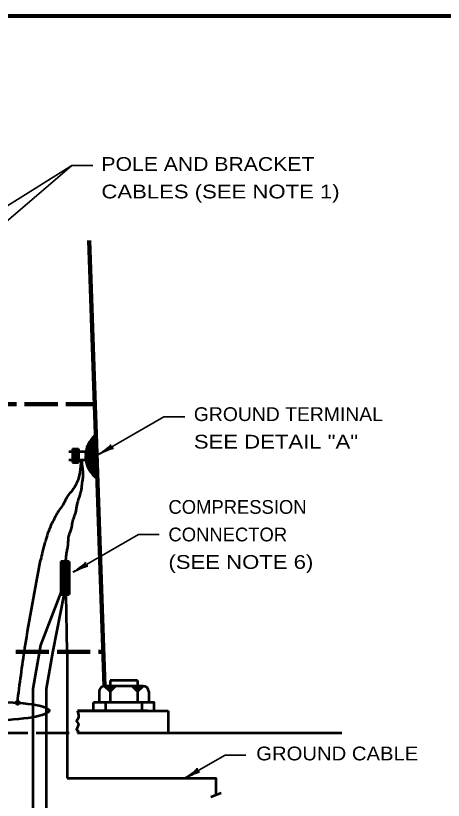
# Model space of a CAD drawing. Extents: x -217 to 639, y -295 to 249.
# Drawn here: x 144.4 to 237.5, y 71.4 to 242.4 of the extents above; entities that cross this region are included whole.
import ezdxf

# ---------------------------------------------------------------- set-up
doc = ezdxf.new("R2010")
doc.units = 0
doc.header["$LTSCALE"] = 1.2
doc.linetypes.add('LONG_DASHED', pattern=[7.5, 6, -1.5])
doc.layers.add('1', color=7, linetype='Continuous', lineweight=53)

msp = doc.modelspace()

# ---------------------------------------------------------------- linework, layer by layer
at = {"layer": '1', "lineweight": 35}
msp.add_line((156.575, 209.728), (133.572, 190.088), dxfattribs=at)
at = {"layer": '1', "lineweight": 90}
msp.add_line((163.725, 96.277), (160.333, 193.418), dxfattribs=at)
at = {"layer": '1', "linetype": 'LONG_DASHED', "lineweight": 90}
for p, q in [((110.301, 157.712), (161.58, 157.712)), ((108.394, 103.712), (163.331, 103.712))]:
    msp.add_line(p, q, dxfattribs=at)
at = {"layer": '1'}
for p, q in [((161.978, 141.739), (161.559, 150.715)), ((161.658, 150.863), (162.028, 141.739)), ((159.66, 147.337), (155.912, 147.337)), ((156.743, 147.995), (156.743, 144.995)), ((156.743, 147.995), (158.023, 147.995)), ((156.743, 147.967), (158.023, 147.967)), ((156.743, 147.959), (158.023, 147.959)), ((156.743, 147.937), (158.023, 147.937)), ((156.743, 147.892), (158.023, 147.892)), ((156.743, 147.884), (158.023, 147.884)), ((156.743, 147.854), (158.023, 147.854)), ((156.743, 147.832), (158.023, 147.832)), ((156.743, 147.832), (158.023, 147.832)), ((156.743, 147.802), (158.023, 147.802)), ((156.743, 147.794), (158.023, 147.794)), ((156.743, 147.794), (158.023, 147.794)), ((156.743, 147.779), (158.023, 147.779)), ((156.743, 147.764), (158.023, 147.764)), ((156.743, 147.749), (158.023, 147.749)), ((156.743, 147.726), (158.023, 147.726)), ((156.743, 147.696), (158.023, 147.696)), ((156.743, 147.689), (158.023, 147.689)), ((156.743, 147.681), (158.023, 147.681)), ((156.743, 147.644), (158.023, 147.644)), ((156.743, 147.629), (158.023, 147.629)), ((156.743, 147.629), (158.023, 147.629)), ((156.743, 147.614), (158.023, 147.614)), ((156.743, 147.606), (158.023, 147.606)), ((156.743, 147.598), (158.023, 147.598)), ((156.743, 147.598), (158.023, 147.598)), ((156.743, 147.576), (158.023, 147.576)), ((156.743, 147.553), (158.023, 147.553)), ((156.743, 147.553), (158.023, 147.553)), ((156.743, 147.538), (158.023, 147.538)), ((156.743, 147.508), (158.023, 147.508)), ((156.743, 147.508), (158.023, 147.508)), ((156.743, 147.486), (158.023, 147.486)), ((156.743, 147.471), (158.023, 147.471)), ((156.743, 147.471), (158.023, 147.471)), ((156.743, 147.441), (158.023, 147.441)), ((156.743, 147.441), (158.023, 147.441)), ((156.743, 147.411), (158.023, 147.411)), ((156.743, 147.403), (158.023, 147.403)), ((156.743, 147.403), (158.023, 147.403)), ((156.743, 147.38), (158.023, 147.38)), ((156.743, 147.373), (158.023, 147.373)), ((156.743, 147.35), (158.023, 147.35)), ((156.743, 147.343), (158.023, 147.343)), ((156.743, 147.305), (158.023, 147.305)), ((156.743, 147.298), (158.023, 147.298)), ((156.743, 147.29), (158.023, 147.29)), ((156.743, 147.29), (158.023, 147.29)), ((156.743, 147.275), (158.023, 147.275)), ((156.743, 147.23), (158.023, 147.23)), ((156.743, 147.23), (158.023, 147.23)), ((156.743, 147.222), (158.023, 147.222)), ((156.743, 147.222), (158.023, 147.222)), ((156.743, 147.2), (158.023, 147.2)), ((156.743, 147.162), (158.023, 147.162)), ((156.743, 147.162), (158.023, 147.162)), ((156.743, 147.147), (158.023, 147.147)), ((156.743, 147.11), (158.023, 147.11)), ((158.023, 147.995), (158.023, 144.995)), ((159.648, 145.537), (155.912, 145.537)), ((156.743, 147.072), (158.023, 147.072)), ((156.743, 147.035), (158.023, 147.035)), ((156.743, 147.019), (158.023, 147.019)), ((156.743, 147.004), (158.023, 147.004)), ((156.743, 146.982), (158.023, 146.982)), ((156.743, 146.944), (158.023, 146.944)), ((156.743, 146.907), (158.023, 146.907)), ((156.743, 146.892), (158.023, 146.892)), ((156.743, 146.862), (158.023, 146.862)), ((156.743, 146.862), (158.023, 146.862)), ((156.743, 146.839), (158.023, 146.839)), ((156.743, 146.816), (158.023, 146.816)), ((156.743, 146.809), (158.023, 146.809)), ((156.743, 146.786), (158.023, 146.786)), ((156.743, 146.786), (158.023, 146.786)), ((156.743, 146.741), (158.023, 146.741)), ((156.743, 146.734), (158.023, 146.734)), ((156.743, 146.696), (158.023, 146.696)), ((156.743, 146.681), (158.023, 146.681)), ((156.743, 146.666), (158.023, 146.666)), ((156.743, 146.621), (158.023, 146.621)), ((156.743, 146.621), (158.023, 146.621)), ((156.743, 146.576), (158.023, 146.576)), ((156.743, 146.553), (158.023, 146.553)), ((156.743, 146.538), (158.023, 146.538)), ((156.743, 146.508), (158.023, 146.508)), ((156.743, 146.508), (158.023, 146.508)), ((156.743, 146.471), (158.023, 146.471)), ((156.743, 146.44), (158.023, 146.44)), ((156.743, 146.395), (158.023, 146.395)), ((156.743, 146.358), (158.023, 146.358)), ((156.743, 146.313), (158.023, 146.313)), ((156.743, 146.29), (158.023, 146.29)), ((156.743, 146.26), (158.023, 146.26)), ((156.743, 146.222), (158.023, 146.222)), ((156.743, 146.2), (158.023, 146.2)), ((156.743, 146.155), (158.023, 146.155)), ((156.743, 146.125), (158.023, 146.125)), ((156.743, 146.102), (158.023, 146.102)), ((156.743, 146.079), (158.023, 146.079)), ((156.743, 146.079), (158.023, 146.079)), ((156.743, 146.049), (158.023, 146.049)), ((156.743, 146.027), (158.023, 146.027)), ((156.743, 146.027), (158.023, 146.027)), ((156.743, 146.004), (158.023, 146.004)), ((156.743, 145.974), (158.023, 145.974)), ((156.743, 145.967), (158.023, 145.967)), ((156.743, 145.929), (158.023, 145.929)), ((156.743, 145.929), (158.023, 145.929)), ((156.743, 145.914), (158.023, 145.914)), ((156.743, 145.906), (158.023, 145.906)), ((156.743, 145.884), (158.023, 145.884)), ((156.743, 145.861), (158.023, 145.861)), ((156.743, 145.861), (158.023, 145.861)), ((156.743, 145.831), (158.023, 145.831)), ((156.743, 145.809), (158.023, 145.809)), ((156.743, 145.771), (158.023, 145.771)), ((156.743, 145.741), (158.023, 145.741)), ((156.743, 145.719), (158.023, 145.719)), ((156.743, 145.704), (158.023, 145.704)), ((156.743, 145.681), (158.023, 145.681)), ((156.743, 145.643), (158.023, 145.643)), ((156.743, 145.606), (158.023, 145.606)), ((156.743, 145.576), (158.023, 145.576)), ((156.743, 145.561), (158.023, 145.561)), ((156.743, 145.553), (158.023, 145.553)), ((156.743, 145.508), (158.023, 145.508)), ((156.743, 145.47), (158.023, 145.47)), ((156.743, 145.425), (158.023, 145.425)), ((156.743, 145.403), (158.023, 145.403)), ((156.743, 145.35), (158.023, 145.35)), ((156.743, 145.328), (158.023, 145.328)), ((156.743, 145.312), (158.023, 145.312)), ((156.743, 145.267), (158.023, 145.267)), ((156.743, 145.237), (158.023, 145.237)), ((156.743, 145.192), (158.023, 145.192)), ((156.743, 145.17), (158.023, 145.17)), ((156.743, 145.139), (158.023, 145.139)), ((156.743, 145.109), (158.023, 145.109)), ((156.743, 145.072), (158.023, 145.072)), ((156.743, 145.064), (158.023, 145.064)), ((156.743, 145.042), (158.023, 145.042)), ((156.743, 145.012), (158.023, 145.012)), ((156.743, 144.995), (158.023, 144.995)), ((156.007, 123.399), (154.207, 123.399)), ((154.357, 123.399), (154.357, 116.199)), ((154.477, 123.399), (154.477, 116.199)), ((154.568, 123.399), (154.568, 116.199)), ((154.628, 123.399), (154.628, 116.199)), ((154.748, 123.399), (154.748, 116.199)), ((154.838, 123.399), (154.838, 116.199)), ((154.899, 123.399), (154.899, 116.199)), ((155.019, 123.399), (155.019, 116.199)), ((155.019, 123.399), (155.019, 116.199)), ((155.079, 123.399), (155.079, 116.199)), ((155.199, 123.399), (155.199, 116.199)), ((155.199, 123.399), (155.199, 116.199)), ((155.26, 123.399), (155.26, 116.199)), ((155.407, 116.199), (155.407, 123.399)), ((155.485, 116.199), (155.485, 123.399)), ((155.561, 116.199), (155.561, 123.399)), ((155.622, 116.199), (155.622, 123.399)), ((155.698, 116.199), (155.698, 123.399)), ((155.759, 116.199), (155.759, 123.399)), ((155.85, 116.199), (155.85, 123.399)), ((155.896, 116.199), (155.896, 123.399)), ((156.007, 123.399), (156.007, 116.199)), ((149.853, 105.153), (154.362, 116.899)), ((152.525, 103.972), (154.897, 116.177)), ((155.565, 103.77), (155.348, 116.202)), ((148.186, 95.699), (149.853, 105.153)), ((151.066, 95.699), (152.525, 103.972)), ((155.565, 103.77), (155.565, 76.17)), ((164.917, 95.074), (163.717, 96.273)), ((172.125, 96.277), (163.725, 96.277)), ((164.925, 95.077), (163.725, 96.277)), ((164.935, 95.091), (163.752, 96.273)), ((164.949, 95.106), (163.778, 96.277)), ((164.949, 95.106), (163.782, 96.273)), ((164.964, 95.121), (163.812, 96.273)), ((164.98, 95.136), (163.842, 96.273)), ((164.987, 95.144), (163.857, 96.273)), ((164.991, 95.147), (163.861, 96.277)), ((165.004, 95.16), (163.887, 96.277)), ((165.006, 95.163), (163.895, 96.273)), ((165.008, 95.164), (163.899, 96.273)), ((165.021, 95.178), (163.925, 96.273)), ((164.981, 95.138), (163.934, 96.185)), ((165.026, 95.183), (163.936, 96.273)), ((165, 95.157), (163.953, 96.204)), ((165.006, 95.162), (163.959, 96.209)), ((165.008, 95.164), (163.961, 96.211)), ((165.008, 95.164), (163.961, 96.211)), ((165.04, 95.197), (163.963, 96.273)), ((165.017, 95.174), (163.97, 96.22)), ((165.023, 95.179), (163.976, 96.226)), ((165.049, 95.206), (163.981, 96.273)), ((165.028, 95.185), (163.981, 96.232)), ((165.051, 95.208), (163.985, 96.273)), ((165.053, 95.209), (164.006, 96.256)), ((165.064, 95.221), (164.017, 96.267)), ((165.068, 95.224), (164.021, 96.271)), ((165.07, 95.227), (164.023, 96.273)), ((165.079, 95.236), (164.037, 96.277)), ((165.083, 95.24), (164.049, 96.273)), ((165.094, 95.251), (164.072, 96.273)), ((165.107, 95.264), (164.094, 96.277)), ((165.109, 95.266), (164.102, 96.273)), ((165.113, 95.27), (164.109, 96.273)), ((165.119, 95.275), (164.121, 96.273)), ((165.128, 95.285), (164.135, 96.277)), ((165.13, 95.287), (164.143, 96.273)), ((165.143, 95.3), (164.165, 96.277)), ((165.145, 95.302), (164.174, 96.273)), ((165.15, 95.307), (164.18, 96.277)), ((165.149, 95.306), (164.181, 96.273)), ((165.162, 95.319), (164.207, 96.273)), ((165.173, 95.33), (164.226, 96.277)), ((165.181, 95.337), (164.24, 96.277)), ((165.186, 95.343), (164.252, 96.277)), ((165.192, 95.349), (164.263, 96.277)), ((165.19, 95.347), (164.264, 96.273)), ((165.198, 95.354), (164.271, 96.281)), ((165.196, 95.353), (164.275, 96.273)), ((165.209, 95.366), (164.297, 96.277)), ((165.209, 95.366), (164.297, 96.277)), ((165.207, 95.364), (164.297, 96.273)), ((165.216, 95.373), (164.312, 96.277)), ((165.224, 95.381), (164.327, 96.277)), ((165.235, 95.392), (164.35, 96.277)), ((165.237, 95.394), (164.353, 96.277)), ((165.243, 95.399), (164.365, 96.277)), ((165.25, 95.407), (164.384, 96.273)), ((165.256, 95.413), (164.391, 96.277)), ((165.266, 95.422), (164.414, 96.273)), ((165.271, 95.428), (164.421, 96.277)), ((165.203, 95.36), (164.423, 96.14)), ((165.279, 95.435), (164.44, 96.273)), ((165.235, 95.392), (164.455, 96.172)), ((165.245, 95.401), (164.465, 96.181)), ((165.265, 95.422), (164.485, 96.202)), ((165.311, 95.467), (164.505, 96.273)), ((165.286, 95.443), (164.506, 96.223)), ((165.312, 95.469), (164.532, 96.249)), ((165.323, 95.48), (164.544, 96.26)), ((165.329, 95.486), (164.549, 96.266)), ((165.337, 95.494), (164.557, 96.273)), ((165.346, 95.503), (164.572, 96.277)), ((165.348, 95.505), (164.579, 96.273)), ((165.356, 95.512), (164.595, 96.273)), ((165.365, 95.522), (164.609, 96.277)), ((165.365, 95.522), (164.609, 96.277)), ((165.374, 95.531), (164.628, 96.277)), ((165.384, 95.54), (164.647, 96.277)), ((165.386, 95.542), (164.651, 96.277)), ((165.388, 95.544), (164.658, 96.273)), ((165.391, 95.548), (164.662, 96.277)), ((165.391, 95.548), (164.662, 96.277)), ((165.399, 95.556), (164.677, 96.277)), ((165.397, 95.554), (164.677, 96.273)), ((165.405, 95.561), (164.688, 96.277)), ((165.416, 95.572), (164.711, 96.277)), ((165.416, 95.573), (164.715, 96.273)), ((165.425, 95.582), (164.73, 96.277)), ((165.435, 95.591), (164.752, 96.273)), ((165.467, 95.623), (164.816, 96.273)), ((165.478, 95.635), (164.835, 96.277)), ((165.489, 95.646), (164.858, 96.277)), ((165.491, 95.648), (164.861, 96.277)), ((164.917, 95.074), (166.117, 96.273)), ((164.925, 97.477), (164.925, 92.677)), ((170.925, 97.477), (164.925, 97.477)), ((164.925, 95.077), (166.125, 96.277)), ((165.521, 95.678), (164.925, 96.273)), ((165.521, 95.678), (164.926, 96.273)), ((165.534, 95.691), (164.948, 96.277)), ((165.536, 95.693), (164.961, 96.268)), ((165.542, 95.699), (164.967, 96.273)), ((165.546, 95.702), (164.971, 96.277)), ((165.549, 95.706), (164.978, 96.277)), ((165.553, 95.71), (164.986, 96.277)), ((165.561, 95.717), (165.001, 96.277)), ((165.57, 95.727), (165.019, 96.277)), ((165.578, 95.734), (165.038, 96.273)), ((165.585, 95.742), (165.049, 96.277)), ((165.593, 95.749), (165.069, 96.273)), ((165.598, 95.755), (165.076, 96.277)), ((165.612, 95.768), (165.106, 96.273)), ((165.625, 95.781), (165.132, 96.273)), ((165.628, 95.785), (165.136, 96.277)), ((165.638, 95.794), (165.155, 96.277)), ((165.657, 95.813), (165.197, 96.273)), ((165.679, 95.836), (165.238, 96.277)), ((165.677, 95.834), (165.238, 96.273)), ((165.683, 95.84), (165.249, 96.273)), ((165.687, 95.843), (165.253, 96.277)), ((165.694, 95.851), (165.268, 96.277)), ((165.698, 95.855), (165.275, 96.277)), ((165.707, 95.864), (165.294, 96.277)), ((165.724, 95.881), (165.328, 96.277)), ((165.677, 95.834), (165.33, 96.181)), ((165.734, 95.89), (165.347, 96.277)), ((165.747, 95.904), (165.373, 96.277)), ((165.77, 95.926), (165.418, 96.277)), ((165.777, 95.934), (165.433, 96.277)), ((165.783, 95.939), (165.448, 96.273)), ((165.549, 95.705), (165.45, 95.804)), ((165.57, 95.726), (165.471, 95.825)), ((165.815, 95.971), (165.512, 96.273)), ((165.621, 95.777), (165.522, 95.876)), ((165.828, 95.985), (165.539, 96.273)), ((165.852, 96.009), (165.588, 96.273)), ((165.696, 95.852), (165.597, 95.951)), ((165.867, 96.024), (165.618, 96.273)), ((165.876, 96.033), (165.632, 96.277)), ((165.882, 96.039), (165.644, 96.277)), ((165.886, 96.043), (165.651, 96.277)), ((165.784, 95.941), (165.685, 96.04)), ((165.928, 96.084), (165.738, 96.273)), ((165.935, 96.092), (165.749, 96.277)), ((165.959, 96.116), (165.798, 96.277)), ((165.918, 96.074), (165.819, 96.173)), ((165.931, 96.087), (165.832, 96.186)), ((165.972, 96.129), (165.873, 96.228)), ((165.978, 96.134), (165.879, 96.233)), ((166.003, 96.159), (165.885, 96.277)), ((165.99, 96.146), (165.891, 96.245)), ((165.993, 96.15), (165.894, 96.249)), ((166.018, 96.175), (165.919, 96.273)), ((166.022, 96.178), (165.922, 96.277)), ((166.027, 96.184), (165.934, 96.277)), ((166.038, 96.195), (165.956, 96.277)), ((166.102, 96.259), (166.084, 96.277)), ((170.925, 95.077), (169.725, 96.277)), ((170.943, 95.095), (169.761, 96.277)), ((170.958, 95.11), (169.79, 96.277)), ((170.958, 95.11), (169.79, 96.277)), ((170.973, 95.125), (169.82, 96.277)), ((170.988, 95.14), (169.85, 96.277)), ((170.995, 95.148), (169.865, 96.277)), ((171.014, 95.166), (169.903, 96.277)), ((171.016, 95.168), (169.907, 96.277)), ((171.029, 95.181), (169.933, 96.277)), ((171.035, 95.187), (169.944, 96.277)), ((171.048, 95.2), (169.971, 96.277)), ((171.048, 95.2), (169.971, 96.277)), ((171.057, 95.21), (169.99, 96.277)), ((171.059, 95.212), (169.993, 96.277)), ((171.071, 95.223), (170.016, 96.277)), ((171.074, 95.227), (170.023, 96.277)), ((171.078, 95.231), (170.031, 96.277)), ((171.102, 95.255), (170.08, 96.277)), ((171.117, 95.27), (170.11, 96.277)), ((171.127, 95.279), (170.129, 96.277)), ((171.138, 95.291), (170.151, 96.277)), ((171.153, 95.306), (170.182, 96.277)), ((171.17, 95.322), (170.215, 96.277)), ((171.18, 95.332), (170.234, 96.277)), ((171.187, 95.339), (170.249, 96.277)), ((171.198, 95.351), (170.272, 96.277)), ((171.204, 95.356), (170.283, 96.277)), ((171.215, 95.368), (170.305, 96.277)), ((171.223, 95.375), (170.321, 96.277)), ((171.236, 95.388), (170.347, 96.277)), ((171.258, 95.411), (170.392, 96.277)), ((171.27, 95.422), (170.415, 96.277)), ((171.274, 95.426), (170.422, 96.277)), ((171.274, 95.426), (170.423, 96.277)), ((171.287, 95.439), (170.448, 96.277)), ((171.296, 95.448), (170.467, 96.277)), ((171.313, 95.465), (170.501, 96.277)), ((171.319, 95.471), (170.513, 96.277)), ((171.334, 95.486), (170.543, 96.277)), ((171.345, 95.497), (170.565, 96.277)), ((171.356, 95.509), (170.588, 96.277)), ((171.364, 95.516), (170.603, 96.277)), ((171.366, 95.518), (170.607, 96.277)), ((171.396, 95.548), (170.667, 96.277)), ((171.405, 95.558), (170.685, 96.277)), ((171.413, 95.565), (170.7, 96.277)), ((171.42, 95.573), (170.716, 96.277)), ((171.42, 95.573), (170.716, 96.277)), ((171.424, 95.577), (170.723, 96.277)), ((171.424, 95.576), (170.723, 96.277)), ((171.43, 95.582), (170.734, 96.277)), ((171.443, 95.595), (170.761, 96.277)), ((171.475, 95.627), (170.825, 96.277)), ((171.488, 95.64), (170.851, 96.277)), ((171.497, 95.65), (170.87, 96.277)), ((170.925, 97.477), (170.925, 92.677)), ((170.925, 95.077), (172.125, 96.277)), ((171.53, 95.682), (170.934, 96.277)), ((171.529, 95.682), (170.934, 96.277)), ((171.535, 95.687), (170.945, 96.277)), ((171.543, 95.695), (170.96, 96.277)), ((171.546, 95.699), (170.968, 96.277)), ((171.55, 95.702), (170.975, 96.277)), ((171.554, 95.706), (170.983, 96.277)), ((171.586, 95.738), (171.047, 96.277)), ((171.601, 95.753), (171.077, 96.277)), ((171.608, 95.761), (171.092, 96.277)), ((171.612, 95.764), (171.099, 96.277)), ((171.62, 95.772), (171.115, 96.277)), ((171.625, 95.778), (171.126, 96.277)), ((171.633, 95.785), (171.141, 96.277)), ((171.639, 95.791), (171.152, 96.277)), ((171.665, 95.817), (171.205, 96.277)), ((171.686, 95.838), (171.246, 96.277)), ((171.691, 95.843), (171.257, 96.277)), ((171.697, 95.849), (171.269, 96.277)), ((171.733, 95.885), (171.34, 96.277)), ((171.742, 95.894), (171.359, 96.277)), ((171.755, 95.907), (171.385, 96.277)), ((171.757, 95.909), (171.389, 96.277)), ((171.778, 95.93), (171.43, 96.277)), ((171.529, 95.681), (171.43, 95.78)), ((171.539, 95.69), (171.44, 95.789)), ((171.791, 95.943), (171.457, 96.277)), ((171.557, 95.709), (171.458, 95.808)), ((171.578, 95.73), (171.479, 95.829)), ((171.823, 95.975), (171.52, 96.277)), ((171.629, 95.781), (171.53, 95.88)), ((171.861, 96.013), (171.596, 96.277)), ((171.704, 95.856), (171.605, 95.955)), ((171.866, 96.018), (171.607, 96.277)), ((171.876, 96.028), (171.626, 96.277)), ((171.881, 96.033), (171.637, 96.277)), ((171.766, 95.918), (171.667, 96.017)), ((171.907, 96.06), (171.69, 96.277)), ((171.826, 95.978), (171.727, 96.077)), ((171.936, 96.088), (171.747, 96.277)), ((171.864, 96.016), (171.765, 96.115)), ((171.909, 96.061), (171.81, 96.16)), ((171.926, 96.078), (171.827, 96.177)), ((171.939, 96.091), (171.84, 96.19)), ((171.98, 96.133), (171.881, 96.232)), ((171.986, 96.138), (171.887, 96.237)), ((171.99, 96.142), (171.891, 96.241)), ((172.01, 96.163), (171.911, 96.262)), ((172.026, 96.178), (171.927, 96.277)), ((172.076, 96.229), (172.028, 96.277)), ((172.085, 96.238), (172.045, 96.278)), ((172.093, 96.245), (172.062, 96.276)), ((172.101, 96.253), (172.08, 96.273)), ((148.186, 61.233), (148.186, 95.699)), ((151.066, 61.271), (151.066, 95.699)), ((162.525, 95.077), (162.525, 92.677)), ((165.07, 95.226), (164.971, 95.325)), ((165.113, 95.269), (165.014, 95.368)), ((165.408, 95.564), (165.309, 95.663)), ((165.485, 95.642), (165.386, 95.741)), ((171.042, 95.194), (170.943, 95.293)), ((171.121, 95.273), (171.022, 95.372)), ((171.206, 95.357), (171.107, 95.456)), ((171.313, 95.465), (171.214, 95.564)), ((171.416, 95.568), (171.317, 95.667)), ((171.431, 95.583), (171.332, 95.682)), ((171.456, 95.608), (171.357, 95.707)), ((171.46, 95.612), (171.361, 95.711)), ((171.494, 95.645), (171.394, 95.744)), ((171.497, 95.649), (171.398, 95.748)), ((173.325, 95.077), (173.325, 92.677)), ((161.325, 90.877), (161.325, 92.677)), ((163.962, 90.877), (163.962, 92.677)), ((171.896, 90.877), (171.896, 92.677)), ((157.786, 90.877), (177.586, 90.877)), ((173.035, 90.877), (157.786, 90.877)), ((177.586, 90.877), (177.586, 86.077)), ((157.786, 86.077), (215.386, 86.077)), ((186.837, 72.16), (189.093, 72.981))]:
    msp.add_line(p, q, dxfattribs=at)
at = {"layer": '1', "linetype": 'LONG_DASHED'}
msp.add_line((112.786, 86.077), (157.786, 86.077), dxfattribs=at)
at = {"layer": '1', "lineweight": 158}
msp.add_lwpolyline([(632.039, 242.399), (-159.661, 242.299), (-159.561, -283.701)], dxfattribs=at)
at = {"layer": '1', "lineweight": 35}
for points in [[(161.133, 209.728), (156.575, 209.728), (128.172, 192.013)], [(181.183, 154.967), (176.625, 154.967), (162.408, 146.76)], [(175.646, 129.298), (171.089, 129.298), (156.872, 121.09)], [(194.521, 81.231), (189.963, 81.231), (181.198, 76.17)]]:
    msp.add_lwpolyline(points, dxfattribs=at)
at = {"layer": '1'}
for points in [[(161.436, 150.641), (161.88, 141.788), (161.337, 150.592), (161.781, 141.862), (161.239, 150.37), (161.683, 141.961), (161.091, 150.271), (161.559, 142.059), (161.14, 150.247), (161.436, 142.207), (160.967, 150.123), (161.313, 142.257), (160.943, 150.049), (161.189, 142.429), (162.102, 141.64), (161.041, 142.553), (160.795, 149.951), (161.584, 150.715), (160.844, 149.827), (161.066, 142.75)], [(160.721, 142.996), (160.376, 149.236), (160.597, 143.169), (160.252, 149.088), (160.499, 143.391), (160.178, 148.792), (160.376, 143.588), (160.055, 148.57), (160.252, 143.835), (159.907, 148.249), (160.129, 144.106), (159.833, 147.805), (160.03, 144.501), (159.759, 147.46), (159.932, 144.673), (159.66, 147.016), (159.808, 145.142), (159.956, 148.2)], [(161.115, 142.725), (160.745, 143.046), (160.499, 149.433), (160.745, 143.07)], [(160.918, 142.824), (160.696, 149.704), (160.918, 142.75), (160.597, 149.581), (160.819, 142.873), (161.165, 142.553)], [(159.981, 147.312), (159.66, 146.153), (159.981, 144.525), (160.425, 143.687), (160.647, 143.169)], [(154.207, 123.399), (154.207, 116.199), (156.007, 116.199)], [(174.525, 90.877), (174.525, 92.677), (161.325, 92.677)], [(157.786, 90.877), (158.048, 89.954), (158.048, 89.352), (157.566, 88.629), (157.928, 88.148), (158.048, 87.907), (157.566, 86.823), (157.928, 86.461), (157.786, 86.077)], [(155.565, 76.17), (187.965, 76.17), (187.965, 72.57)]]:
    msp.add_lwpolyline(points, dxfattribs=at)
for centre, radius in [((144.802, 92.647), 0.36), ((144.787, 92.658), 0.332), ((144.791, 92.651), 0.298), ((144.776, 92.654), 0.26), ((144.791, 92.639), 0.253), ((144.614, 92.643), 0.0643), ((144.798, 92.673), 0.243), ((144.787, 92.673), 0.209), ((144.776, 92.681), 0.171), ((144.787, 92.684), 0.14), ((144.757, 92.647), 0.1), ((144.701, 92.496), 0.037), ((144.768, 92.677), 0.0894), ((144.776, 92.733), 0.079), ((144.798, 92.692), 0.0975), ((144.772, 92.793), 0.0678), ((144.81, 92.756), 0.0858), ((144.765, 92.688), 0.0241), ((144.832, 92.485), 0.0828), ((144.813, 92.681), 0.0479), ((144.844, 92.466), 0.0155), ((144.84, 92.493), 0.0084), ((144.866, 92.515), 0.0287), ((144.904, 92.647), 0.0188), ((144.93, 92.745), 0.0376), ((144.998, 92.609), 0.0481), ((145.024, 92.696), 0.0159)]:
    msp.add_circle(centre, radius, dxfattribs=at)
for centre, radius, start, end in [((165.571, 146.398), 5.985, 128.68208, 235.31633), ((163.725, 95.077), 1.2, 90, 180), ((172.125, 95.077), 1.2, 0, 90)]:
    msp.add_arc(centre, radius, start, end, dxfattribs=at)
at = {"layer": '1', "lineweight": 40}
for centre, major_axis, ratio, start_param, end_param in [((163.377, 147.701), (-1.762, -1.234), 0.122415, 0.8963533, 3.1415927), ((163.377, 147.701), (-1.762, -1.234), 0.122415, 0.8963533, 3.1415927), ((163.7, 147.212), (1.931, 0.871), 0.07063, 6.2823074, 8.5597026), ((163.7, 147.212), (1.931, 0.871), 0.07063, 6.2823074, 8.5597026), ((157.84, 122.032), (-1.762, -1.234), 0.122415, 0.8963533, 3.1415927), ((157.84, 122.032), (-1.762, -1.234), 0.122415, 0.8963533, 3.1415927), ((158.163, 121.543), (1.931, 0.871), 0.07063, 6.2823074, 8.5597026), ((158.163, 121.543), (1.931, 0.871), 0.07063, 6.2823074, 8.5597026), ((182.166, 77.112), (-1.762, -1.234), 0.122415, 0.8963533, 3.1415927), ((182.489, 76.623), (1.931, 0.871), 0.07063, 6.2823074, 8.5597026)]:
    msp.add_ellipse(centre, major_axis=major_axis, ratio=ratio, start_param=start_param, end_param=end_param, dxfattribs=at)
at = {"layer": '1'}
msp.add_ellipse((138.867, 90.743), major_axis=(-12.767, -0.191), ratio=0.158809, dxfattribs=at)
for points in [[(158.579, 145.537), (157.564, 140.332), (156.722, 139.009), (155.519, 137.445), (154.797, 136.001), (153.955, 134.798), (152.752, 132.753), (152.03, 131.31), (151.308, 129.505), (150.827, 127.821), (150.466, 126.739), (150.226, 125.656), (149.744, 123.731)], [(158.707, 145.49), (158.767, 144.768), (158.887, 143.746), (158.947, 143.024), (159.007, 142.062), (158.887, 141.22), (158.707, 139.896), (158.586, 138.994), (158.346, 138.032), (157.864, 136.528), (157.564, 135.085), (157.383, 134.182), (157.022, 133.1), (156.661, 131.897), (156.421, 130.633), (156.12, 129.731), (155.819, 128.649), (155.759, 127.927), (155.699, 126.964), (155.519, 125.942), (155.338, 125.04), (155.278, 124.198), (155.158, 123.416), (155.037, 123.055)], [(158.707, 145.49), (158.696, 145.504), (158.696, 145.531)], [(144.716, 92.73), (146.376, 104.604), (149.744, 123.731)]]:
    msp.add_spline(points, degree=3, dxfattribs=at)

# ---------------------------------------------------------------- texts
for s, width, p in [('POLE AND BRACKET', 1.15, (163.026, 208.571)), ('CABLES (SEE NOTE 1)', 1.2, (163.026, 202.571)), ('GROUND TERMINAL', 1.05, (183.171, 154.043)), ('SEE DETAIL "A"', 1.2, (183.171, 148.043)), ('(SEE NOTE 6)', 1.2, (177.635, 121.817)), ('GROUND CABLE', 1.1, (196.761, 80.075))]:
    msp.add_text(s, height=3, dxfattribs=dict(at, width=width)).set_placement(p)
for s, p in [('COMPRESSION', (177.635, 133.817)), ('CONNECTOR', (177.635, 127.817))]:
    msp.add_text(s, height=3, dxfattribs=at).set_placement(p)

doc.saveas('drawing.dxf')
